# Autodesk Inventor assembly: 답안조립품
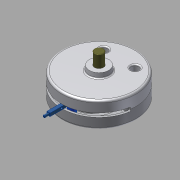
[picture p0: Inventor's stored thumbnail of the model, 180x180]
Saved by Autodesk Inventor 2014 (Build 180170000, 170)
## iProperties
Created: 2015-06
Part Number: 답안조립품
Document SubType Name: Assembly
Designer: MYHOME
Author: MYHOME
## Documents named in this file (9)
- C:\Documents and Settings\MYHOME\바탕 화면\450631V1043\450631V1043\답안조립품.iam
- C:\Documents and Settings\MYHOME\바탕 화면\450631V1043\450631V1043\본체.ipt
- C:\Documents and Settings\MYHOME\바탕 화면\450631V1043\450631V1043\베어링62_22.ipt
- C:\Documents and Settings\MYHOME\바탕 화면\450631V1043\450631V1043\덮개.ipt
- C:\Documents and Settings\MYHOME\바탕 화면\450631V1043\450631V1043\M10x35.ipt
- C:\Documents and Settings\MYHOME\바탕 화면\450631V1043\450631V1043\축.ipt
- C:\Documents and Settings\MYHOME\바탕 화면\450631V1043\450631V1043\슬라이더2.ipt
- C:\Documents and Settings\MYHOME\바탕 화면\450631V1043\450631V1043\멈춤링.ipt
- C:\Documents and Settings\MYHOME\바탕 화면\450631V1043\450631V1043\슬라이더.ipt
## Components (6 placed, 3 different names)
1. KS B 2023 62/22 - 22 x 50 x 14:1
2. KS B 2023 62/22 - 22 x 50 x 14:2
3. KS B 1003 - 미터 M 10 x 35:1
4. KS B 1003 - 미터 M 10 x 35:2
5. KS B 1336 22 x 1.2:1
6. KS B 1336 22 x 1.2:2
